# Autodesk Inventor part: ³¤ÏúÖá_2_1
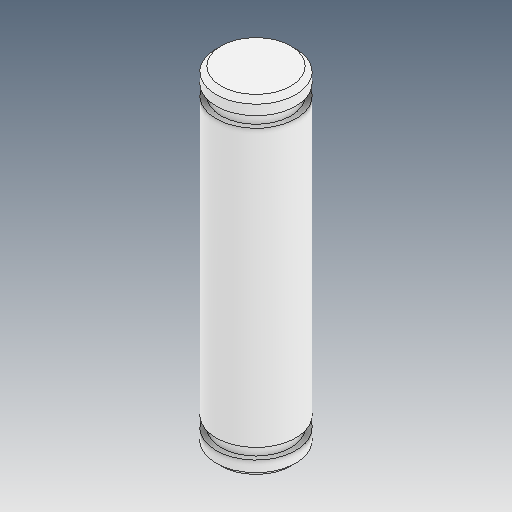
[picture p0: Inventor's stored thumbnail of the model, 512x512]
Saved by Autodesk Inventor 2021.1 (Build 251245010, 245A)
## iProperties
Created: 2021-05
Part Number: ³¤ÏúÖá_2_1
Material: Ogólny
Document SubType Name: Modeling
Designer: user
Density: 1 g/cm^3
Appearance: Domyślna
Author: user
Revision Number: ÈÎºÎ
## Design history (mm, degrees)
feature "ÊäÈë1"
node "Bryła1"
